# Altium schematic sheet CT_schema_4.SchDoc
size 254 x 245 mm
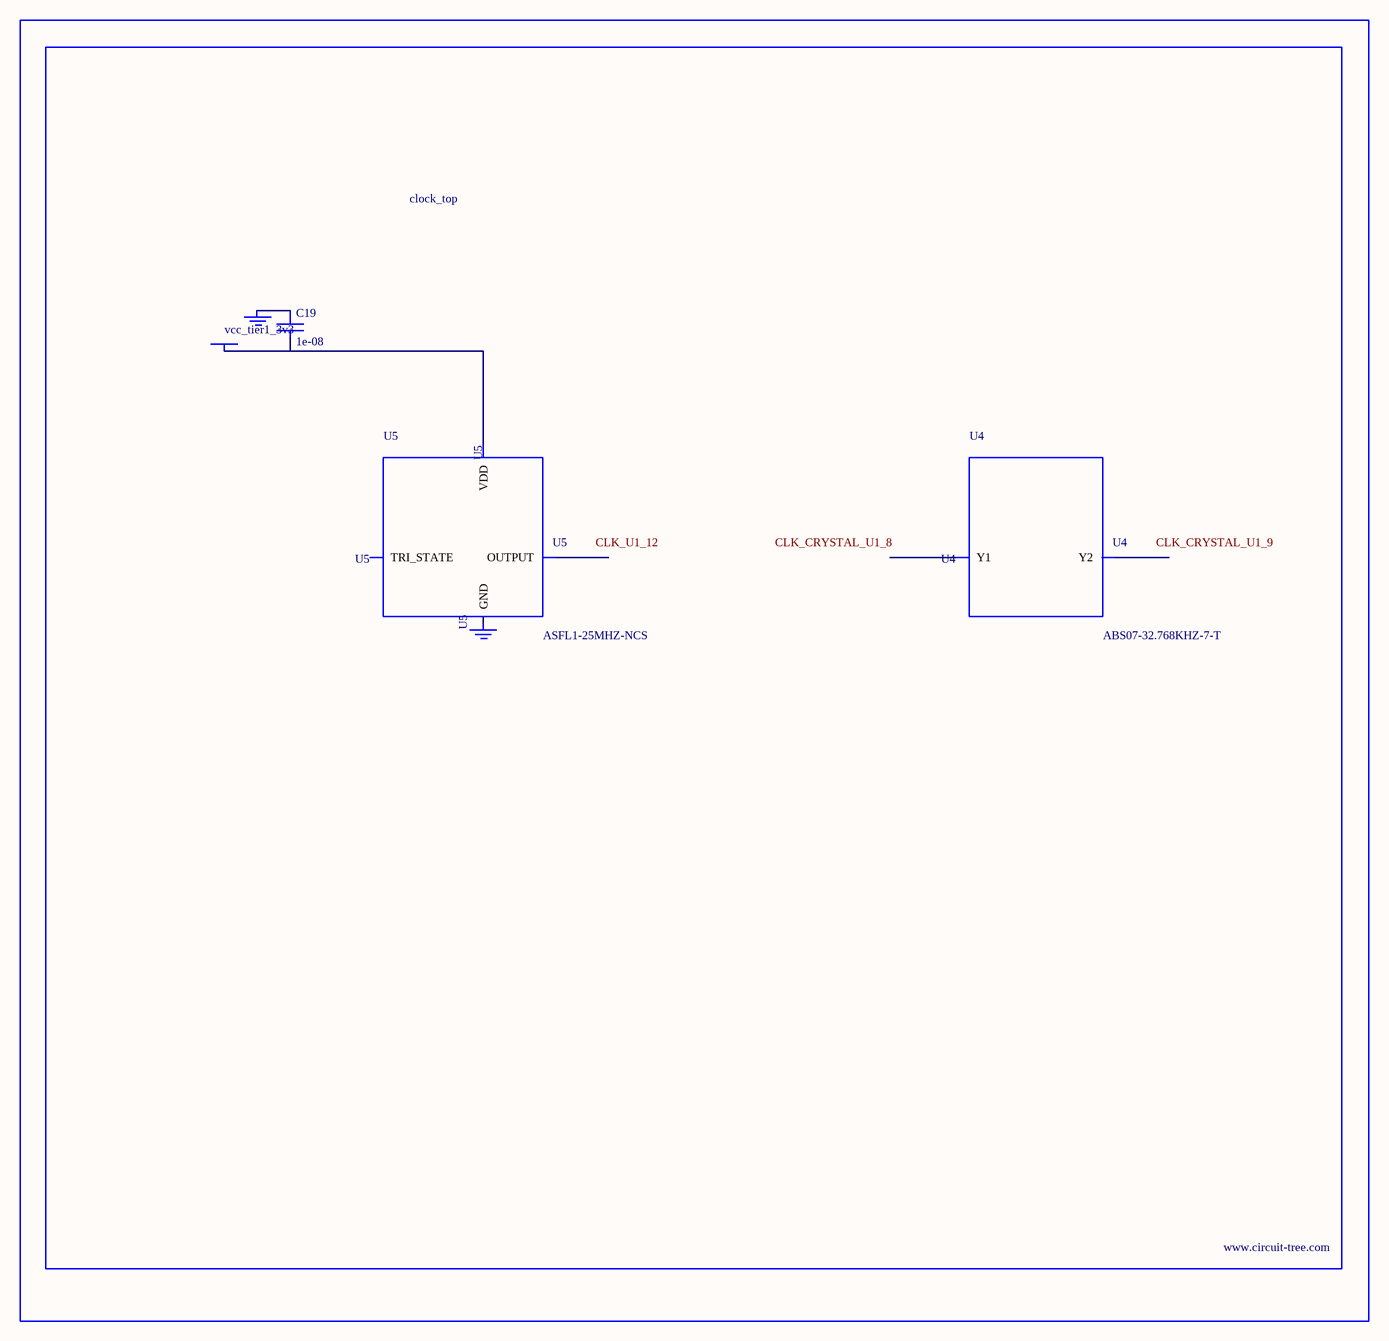
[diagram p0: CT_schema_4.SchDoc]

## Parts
BORDER3  (no value)
C19  1e-08  [C0402]
GND_INSTANCE_3_0  (no value)
GND_INSTANCE_3_1  (no value)
POWER_INSTANCE_3_0  vcc_tier1_3v3
U4  ABS07-32.768KHZ-7-T  [ABS07-32.768KHZ-7-T]
U5  ASFL1-25MHZ-NCS  [ASFL1]

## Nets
NetC19_1: C19.1 GND_INSTANCE_3_0.0(GND)
NetC19_2: C19.2 POWER_INSTANCE_3_0.0(PWR) U5.4(VDD)

Not connected (* = marked no-connect by the designer): GND_INSTANCE_3_1 0(GND); U4 1(Y1) 2(Y2); U5 1(TRI_STATE) 2(GND) 3(OUTPUT)

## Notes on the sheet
- Labels drawn without touching a wire or pin: CLK_CRYSTAL_U1_8, CLK_CRYSTAL_U1_9, CLK_U1_12

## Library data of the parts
BORDER3 = BORDER_PAGE3
C19 = C0402C103K3RAC
GND_INSTANCE_3_0 GND_INSTANCE_3_1 = GND
POWER_INSTANCE_3_0 = PWR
